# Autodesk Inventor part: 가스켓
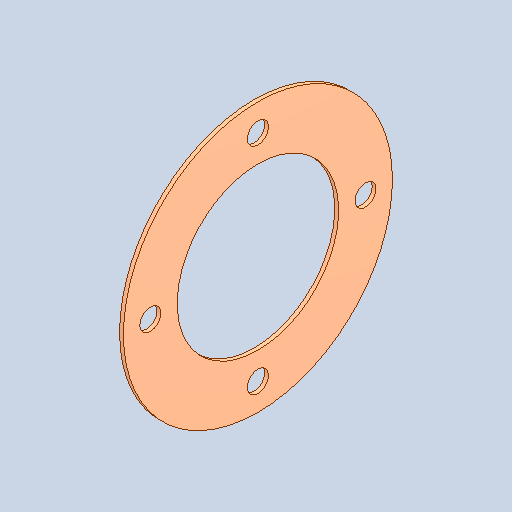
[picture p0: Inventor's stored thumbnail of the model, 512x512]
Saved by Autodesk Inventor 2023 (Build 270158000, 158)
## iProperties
Created: 2024-09
Part Number: 가스켓
Material: 스테인리스스틸
Document SubType Name: Modeling
Designer: home
Density: 8 g/cm^3
Appearance: 기본값
Author: jhkim
Sending System: Autodesk Inventor 2025
Preprocessor: ST-DEVELOPER v20
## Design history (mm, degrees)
feature "솔리드1"
node "솔리드2"
